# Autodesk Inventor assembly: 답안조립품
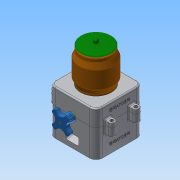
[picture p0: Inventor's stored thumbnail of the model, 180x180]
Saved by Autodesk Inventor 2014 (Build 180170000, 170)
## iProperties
Created: 2018-01
Part Number: 답안조립품
Document SubType Name: Assembly
Designer: NET
Author: NET
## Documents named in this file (9)
- C:\Users\NET\Desktop\480107V1037\답안조립품.iam
- C:\Users\NET\Desktop\480107V1037\답안본체.ipt
- C:\Users\NET\Desktop\480107V1037\핸들축.ipt
- C:\Users\NET\Desktop\480107V1037\핸들.ipt
- C:\Users\NET\Desktop\480107V1037\볼트 M3x12.ipt
- C:\Users\NET\Desktop\480107V1037\본체커버.ipt
- C:\Users\NET\Desktop\480107V1037\용기.ipt
- C:\Users\NET\Desktop\480107V1037\용기캡.ipt
- C:\Users\NET\Desktop\480107V1037\볼트 M4x12.ipt
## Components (2 placed, 2 different names)
1. 핸들축:1
2. 핸들:1
